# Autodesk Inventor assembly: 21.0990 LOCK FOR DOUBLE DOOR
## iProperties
Created: 2007-03
Part Number: 21.0990 LOCK FOR DOUBLE DOOR
Document SubType Name: Assembly
Designer: Andy Moles
Author: Andy Moles
